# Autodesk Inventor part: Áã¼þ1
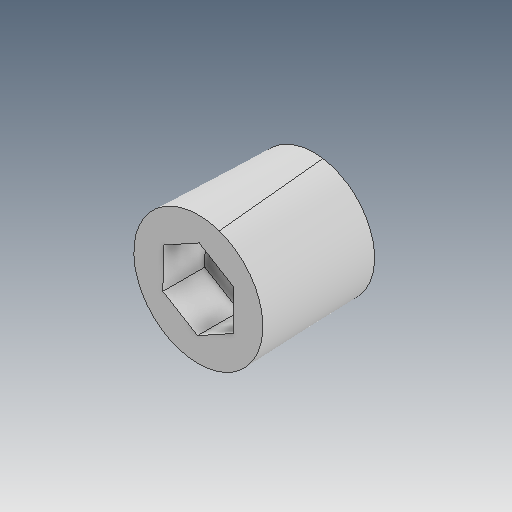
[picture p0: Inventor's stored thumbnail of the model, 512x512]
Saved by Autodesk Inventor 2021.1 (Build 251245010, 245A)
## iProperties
Created: 2013-04
Part Number: Áã¼þ1
Material: Ogólny
Document SubType Name: Modeling
Designer: user
Density: 1 g/cm^3
Appearance: Domyślna
Author: user
Revision Number: ÈÎºÎ
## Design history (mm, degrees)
feature "ÇÐ³ý-À­Éì1"
node "Bryła1"
